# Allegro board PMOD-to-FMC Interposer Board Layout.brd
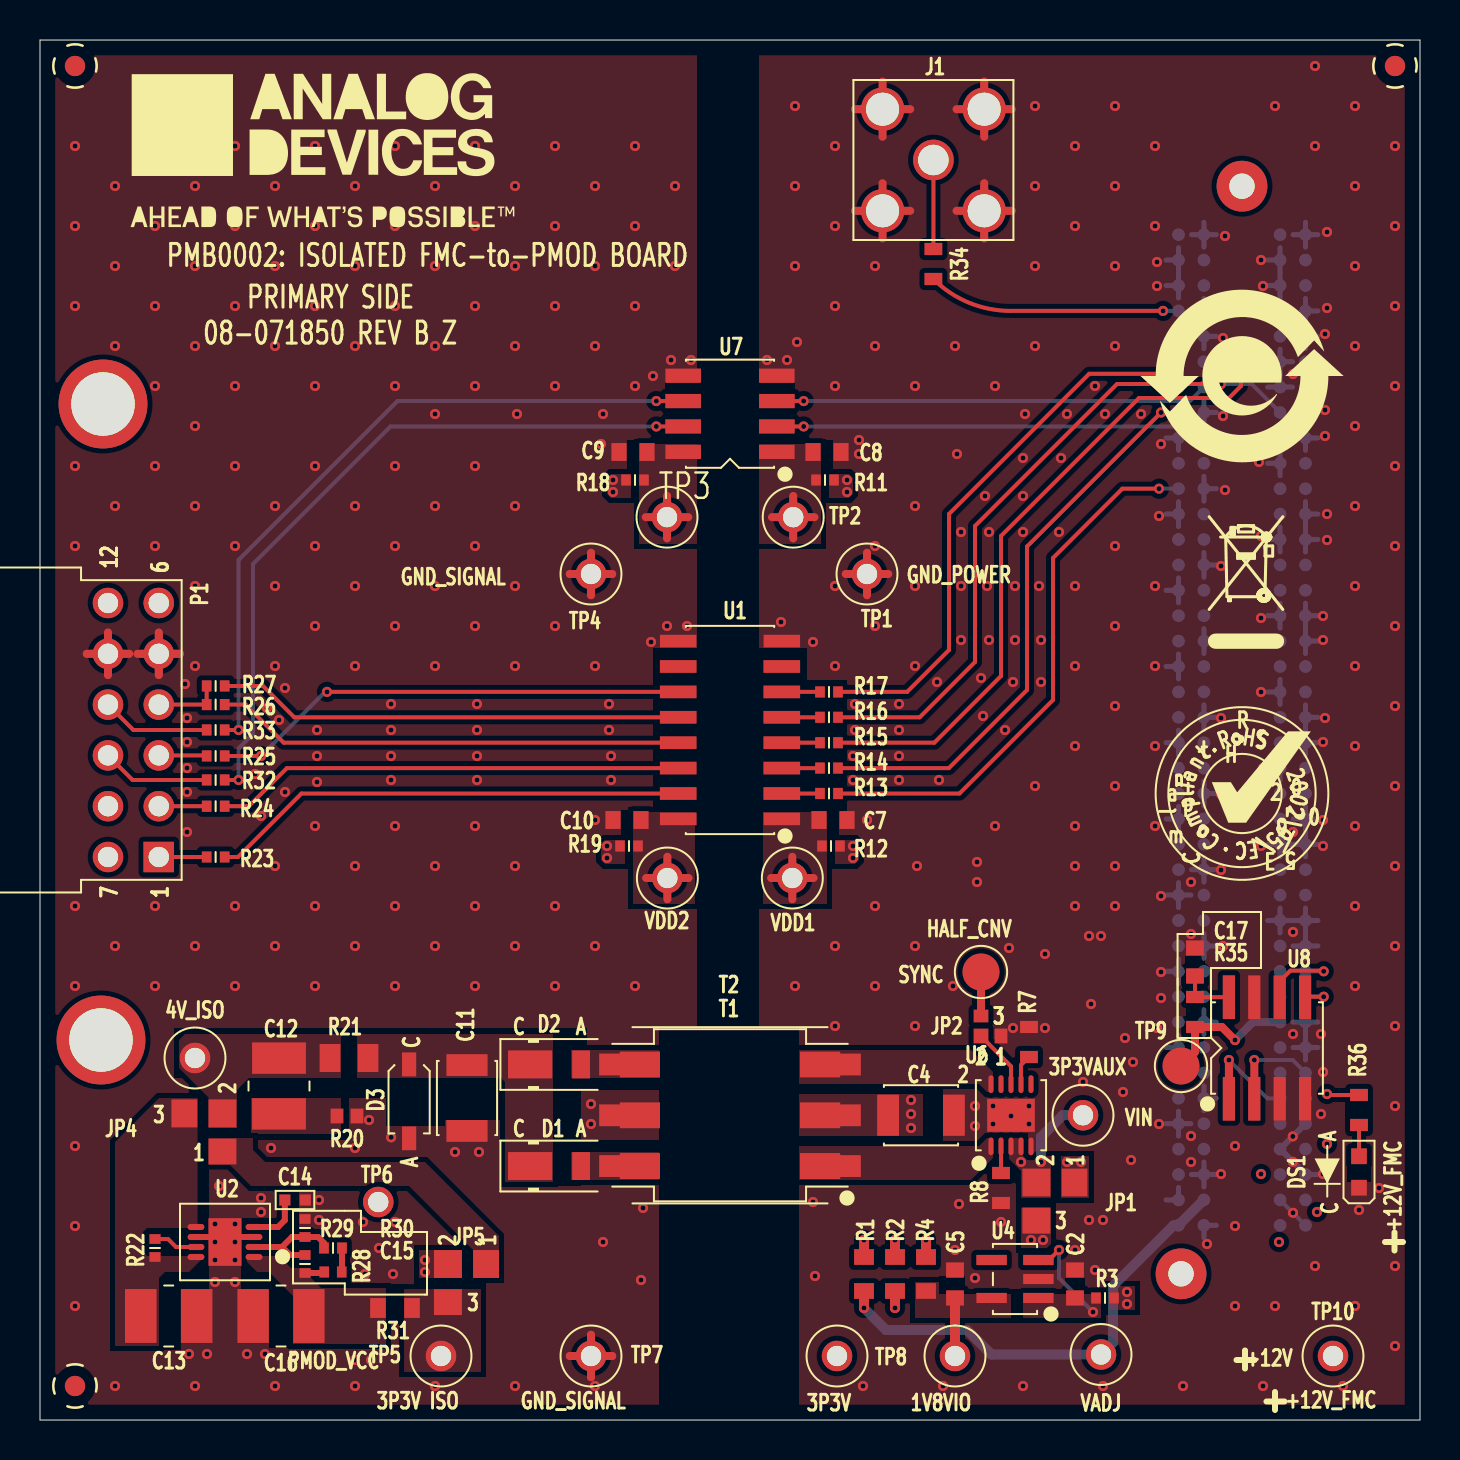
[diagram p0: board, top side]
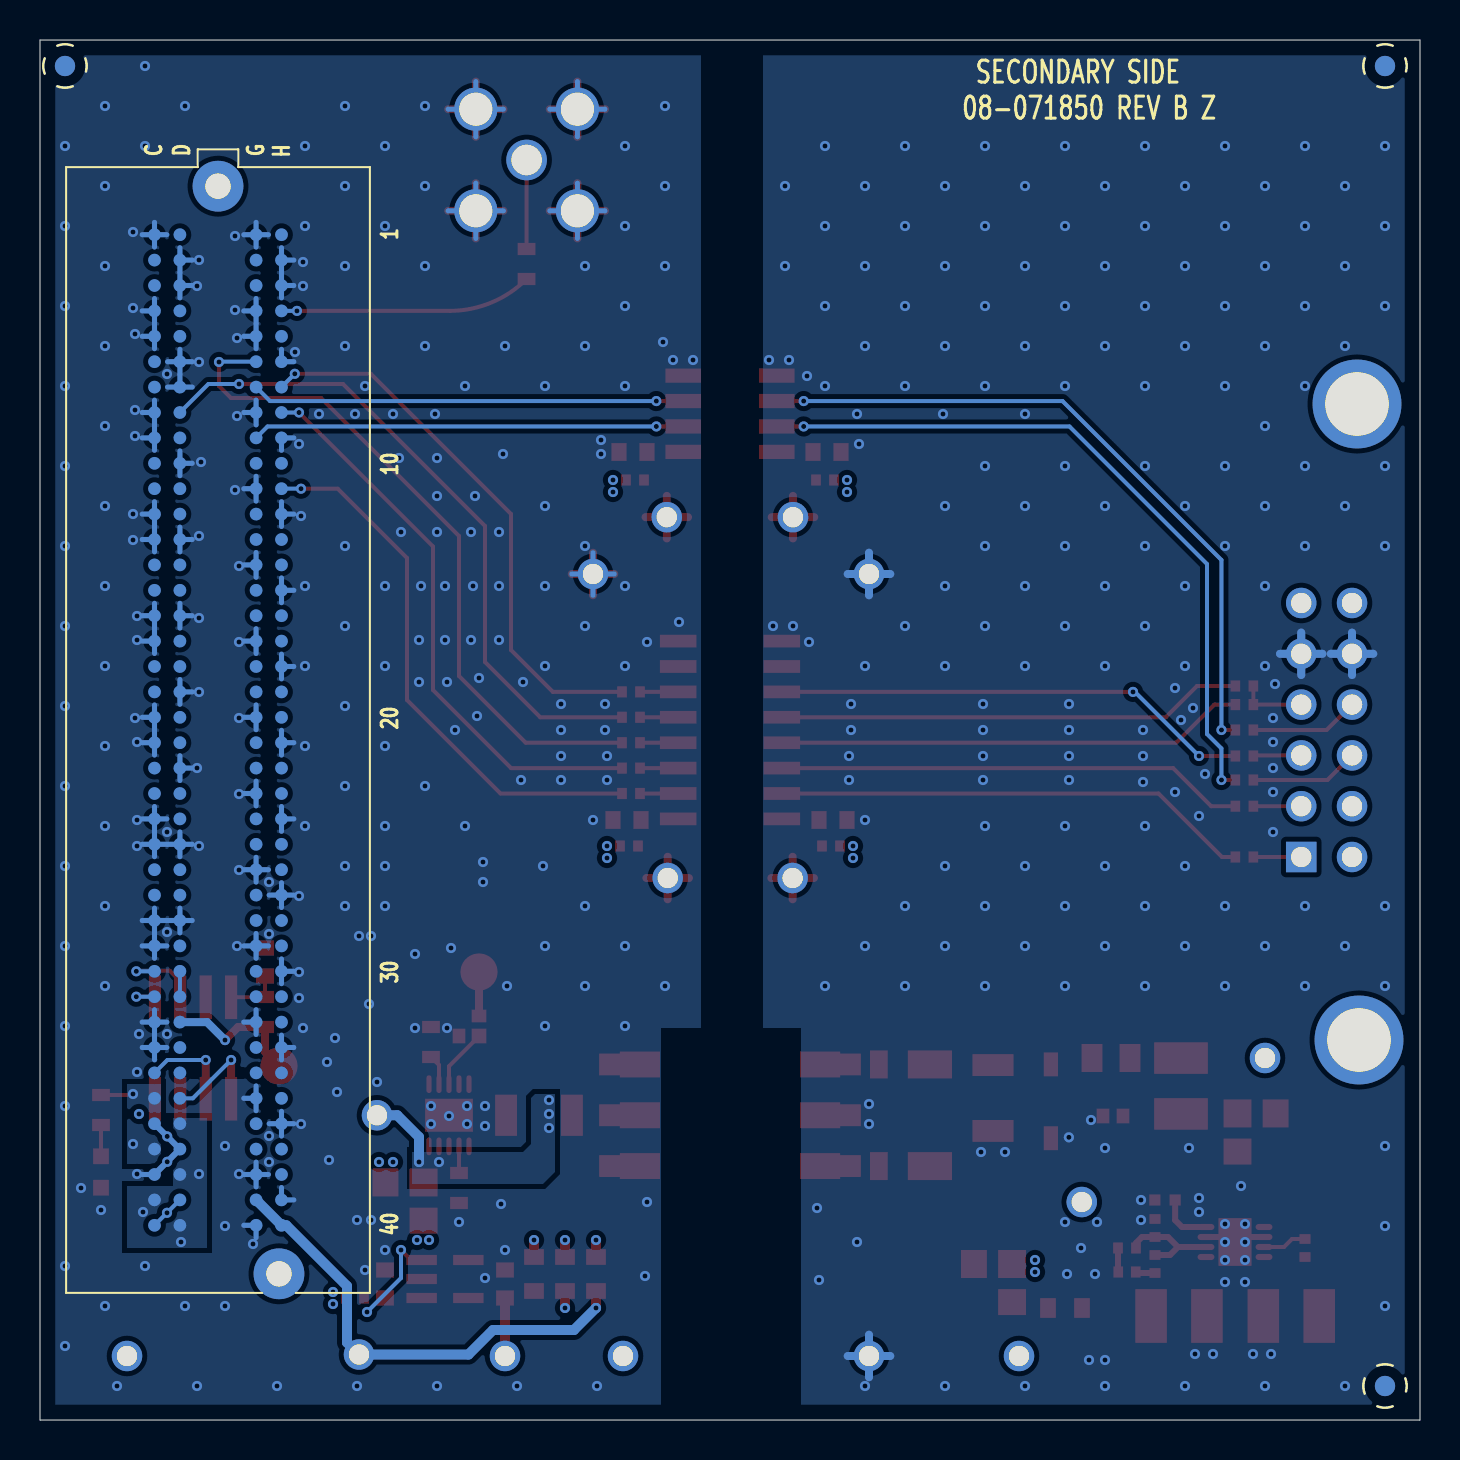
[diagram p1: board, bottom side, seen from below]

Outline 69 x 69 mm; copper layers: TOP, L2_GND, L3_PWR, BOTTOM. Coordinates in mm from the lower left corner of the outline.
Outline path: 0,69 69,69 69,0 0,0 0,69

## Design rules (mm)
constraint set DEFAULT: 

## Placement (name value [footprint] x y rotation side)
C2  1uF  [C0603]  51.75 6.8 90 top
C4  10uF  [C1210H106]  44.05 15.24 0 top
C5  1uF  [C0603]  45.75 6.8 90 top
C7  0.1uF  [C0603]  39.65 30 0 top
C8  0.1uF  [C0603]  39.35 48.4 0 top
C9  0.1uF  [C0603]  29.65 48.4 180 top
C10  0.1uF  [C0603]  29.35 30 180 top
C11  10uF  [C1210H106]  21.35 16.1 270 top
C12  4.7uF  [C1210-2]  11.95 16.7 270 top
C13  4.7uF  [C1210-2]  6.44 5.2 0 top
C14  1NF  [C0402]  12.75 11 0 top
C15  TBD0402  [C0402#2]  14.65 7.4 0 top
C16  4.7uF  [C1210-2]  12.05 5.2 180 top
C17  0.1uF  [C0603]  57.75 22.9 270 top
D1  DFLS240L-7  [POWERDI123]  25.45 12.7 0 top
D2  DFLS240L-7  [POWERDI123]  25.45 17.78 0 top
D3  CMHZ5236B  [SOD123-3]  18.46 15.93 270 top
DS1  SML-LX0603GW-TR  [LED0603-2]  65.95 12.4 90 top
J1  5-1814832-2  [CNTYCO1814832]  44.67 63 180 top
JP1  0  [3PINJUMPER_0603]  50.77 11.88 180 top
JP2  0  [3PINJUMPER_0402]  47.05 19.2 270 top
JP4  0  [3PINJUMPER_0603]  9.12 14.38 90 top
JP5  0  [3PINJUMPER_0603]  21.35 7.8 180 top
NOREF  -  []  0 69 270 top
NOREF#2  -  []  60.1 38.62 0 top
NOREF#3  -  []  90.1 114.4 0 top
NOREF#4  -  [unnamed#2]  1.75 67.7 0 top
NOREF#5  -  []  -62.9 -34.1 0 top
NOREF#6  -  []  156.1 301.8 0 top
NOREF#7  -  []  0.93 50.75 0 top
NOREF#8  -  []  56.4 143.2 0 top
NOREF#9  -  []  69 0 90 top
NOREF#10  -  []  0 69 0 top
NOREF#11  -  []  14.15 63.47 0 top
NOREF#12  -  []  0 69 0 top
NOREF#13  -  []  34.5 85.15 0 top
NOREF#14  -  [unnamed#2]  3.15 50.8 0 top
NOREF#15  -  [unnamed#2]  1.75 1.7 0 top
NOREF#16  -  []  69 69 180 top
NOREF#17  -  []  69 0 90 top
NOREF#18  -  []  69 0 0 top
NOREF#19  -  []  60.1 52.2 0 top
NOREF#20  -  []  0 0 0 top
NOREF#21  -  []  33.8 344.5 0 top
NOREF#22  -  []  0 0 0 top
NOREF#23  -  [unnamed#2]  67.75 67.7 0 top
NOREF#24  -  [unnamed#2]  3.05 19 0 top
NOREF#25  -  []  60.1 31.32 0 top
NOREF#26  -  []  0 0 0 top
NOREF#27  -  []  -112.8 -103 0 top
NOREF#28  -  [unnamed#2]  1.75 67.7 180 bottom
NOREF#29  -  [unnamed#2]  1.75 1.7 180 bottom
NOREF#30  -  [unnamed#2]  67.75 67.7 180 bottom
P1  PPPC062LJBN-RC  [CNHDRRA2X6H205]  5.94 28.15 90 top
P2  ASP-134604-01  [CNSAMTECASP-134604-01]  60.1 34.5 270 bottom
R1  0  [R0603]  41.2 7.3 90 top
R2  0  [R0603]  42.75 7.3 90 top
R3  0  [R0402]  53.25 6.1 180 top
R4  0  [R0603]  44.3 7.3 90 top
R7  36.5K  [R0603]  49.45 18.9 90 top
R8  49.9K  [R0603]  48.05 11.6 270 top
R11  0  [R0402]  39.25 47 180 top
R12  0  [R0402]  39.55 28.7 180 top
R13  0  [R0402]  39.45 31.32 180 top
R14  0  [R0402]  39.45 32.59 180 top
R15  0  [R0402]  39.45 33.87 180 top
R16  0  [R0402]  39.45 35.13 180 top
R17  0  [R0402]  39.45 36.41 180 top
R18  0  [R0402]  29.75 47 180 top
R19  0  [R0402]  29.45 28.7 180 top
R20  0  [R0402]  15.35 15.2 0 top
R21  0  [R0805]  15.45 18.1 180 top
R22  100K  [R0402]  5.75 8.6 90 top
R23  0  [R0402]  8.78 28.15 180 top
R24  0  [R0402]  8.78 30.69 180 top
R25  0  [R0402]  8.78 33.2 180 top
R26  0  [R0402]  8.78 35.77 180 top
R27  0  [R0402]  8.78 36.7 180 top
R28  0  [R0402]  13.25 7.8 90 top
R29  TBD0402  [R0402]  13.25 9.6 90 top
R30  TBD0402  [R0402]  14.65 8.6 0 top
R31  0  [R0603]  17.75 5.6 0 top
R32  0  [R0402]  8.78 32 0 top
R33  0  [R0402]  8.78 34.5 0 top
R34  TBD0603  [R0603]  44.67 57.8 270 top
R35  0  [R0603]  57.75 20.4 90 top
R36  2.4K  [R0603]  65.95 15.5 270 top
SYNC  4956-1-00-15-00-00-33-0  [CNMILLMAX4956]  47.05 22.4 0 top
T1  PH9085.083NLT  [TSML319W280H200]  34.5 15.24 90 top
T2  750315371  [TSML364W327H161]  34.5 15.24 180 top
TP1  BLK  [CNKEY5001TP]  41.35 42.3 90 top
TP2  RED  [CNKEY5001TP]  37.66 45.14 0 top
TP3  RED  [CNKEY5001TP]  31.35 45.14 0 top
TP4  BLK  [CNKEY5001TP]  27.55 42.3 0 top
TP5  RED  [CNKEY5001TP]  20.05 3.2 0 top
TP6  RED  [CNKEY5001TP]  16.91 10.9 0 top
TP7  BLK  [CNKEY5001TP]  27.55 3.2 0 top
TP8  RED  [CNKEY5001TP]  39.85 3.2 0 top
TP9  4956-1-00-15-00-00-33-0  [CNMILLMAX4956]  57.05 17.7 0 top
TP10  RED  [CNKEY5001TP]  64.65 3.2 0 top
U1  ADUM152N1BRZ  [SO16NB-2]  34.5 34.5 90 top
U2  ADP7105ACPZ-3.3  [DFN8_3X3_PAD2_38X1_64]  9.25 8.9 90 top
U4  ADP150AUJZ-1.8  [TSOT-5]  48.75 7.05 90 top
U6  LT3999EDD#PBF  [DFN10_3X3_PAD2_38X1_64]  48.55 15.24 0 top
U7  ADUM120N0BRZ  [SO8-2]  34.5 50.31 90 top
U8  M24C02-WMN6TP  [SO8]  61.35 18.6 0 top
UNK1V8VIO  RED  [CNKEY5001TP]  45.75 3.2 0 top
UNK4V_ISO  RED  [CNKEY5001TP]  7.75 18.1 0 top
VADJ  RED  [CNKEY5001TP]  53.05 3.27 180 top
VDD1  RED  [CNKEY5001TP]  37.62 27.1 0 top
VDD2  RED  [CNKEY5001TP]  31.37 27.1 0 top
VIN  RED  [CNKEY5001TP]  52.15 15.24 0 top

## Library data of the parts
C2 C5 = CAP: User Part Number: UPN; Tolerance: 10; alternate symbols: (C0603L); part number: CAP_SM-1UF,16V,10,E020111,C0603; tolerance: 10
C4 C11 = CAP: Tolerance: 10; User Part Number: UPN; alternate symbols: (); part number: CAP_SM-10UF,25V,10,E013830,C1210H106; tolerance: 10
C7-C10 = CAP: User Part Number: UPN; Tolerance: 10; alternate symbols: (C0603L); part number: CAP_SM-0.1UF,25V,10,E013746,C0603; tolerance: 10
C12 C13 C16 = CAP: Tolerance: 10; User Part Number: UPN; alternate symbols: (); part number: CAP_SM-4.7UF,50V,10,E030852,C1210-2; tolerance: 10
C14 = CAP: User Part Number: UPN; Tolerance: 10; alternate symbols: (C0402L); part number: CAP_SM-1NF,25V,10,E042764,C0402; tolerance: 10
C15 = CAP: User Part Number: UPN; alternate symbols: (C0402L_ALT,C0402L); part number: CAP_SM-TBD0402,TBD0402,TBD0402,E000381,C0402
C17 = CAP: User Part Number: UPN; Tolerance: 10; alternate symbols: (C0603L); part number: CAP_SM-0.1UF,50V,10,E011865,C0603; tolerance: 10
D1 D2 = DIOSCHOTTKY: User Part Number: UPN; Tolerance: N/A; alternate symbols: (); part number: DIOSCHOTTKY_SM-DFLS240L-7,40V,N/A,E022336,POWERDI123; tolerance: N/A
D3 = DIOZNR: Tolerance: 5; User Part Number: UPN; alternate symbols: (); part number: DIOZNR_SM-CMHZ5236B,7.5V,5,E033510,SOD123-3; tolerance: 5
DS1 = DIOLED: Tolerance: N/A; User Part Number: UPN; alternate symbols: (); part number: DIOLED_SM-SML-LX0603GW-TR,N/A,N/A,E018702,LED0603-2; tolerance: N/A
J1 = CNBNC5P: Tolerance: N/A; User Part Number: UPN; alternate symbols: (); part number: CNBNC5P_TH-5-1814832-2,E010606,CNTYCO1814832; tolerance: N/A
JP1 JP4 JP5 = RESJMPRSHRT_3P: Tolerance: JUMPER; User Part Number: UPN; alternate symbols: (); part number: RESJMPRSHRT_3P_SM-0,E004207,1/10W,JUMPER,3PINJUMPER_0603; tolerance: JUMPER
JP2 = RESJMPR_3P: User Part Number: UPN; Tolerance: JUMPER; alternate symbols: (3PINJUMPER_0402_AB, 3PINJUMPER_0402_BA); part number: RESJMPR_3P_SM-0,E003438,1/10W,JUMPER,3PINJUMPER_0402; tolerance: JUMPER
P1 = CN12P_V3: User Part Number: UPN; Tolerance: N/A; alternate symbols: (); part number: CN12P_V3_TH-PPPC062LJBN-RC,E022332,CNHDRRA2X6H205; tolerance: N/A
P2 = CN160P_CDGH_V2: User Part Number: UPN; Tolerance: N/A; alternate symbols: (CNSAMTECASP-134604-01_KITTRF,CNSAMTECASP-134604-01_EVKP); part number: CN160P_CDGH_V2_SM-ASP-134604-01,E011383,CNSAMTECASP-134604-01; tolerance: N/A
R1 R2 R4 R31 = RES: User Part Number: UPN; Tolerance: JUMPER; alternate symbols: (R0603L); part number: RES_SM-0,E006826,1/10W,JUMPER,R0603; tolerance: JUMPER
R3 R11-R20 R23-R28 R32 R33 = RES: User Part Number: UPN; Tolerance: JUMPER; alternate symbols: (R0402L,R0402L_ALT); part number: RES_SM-0,E003438,1/10W,JUMPER,R0402; tolerance: JUMPER
R7 = RES: User Part Number: UPN; Tolerance: 1; alternate symbols: (R0603L); part number: RES_SM-36.5K,E011130,1/10W,1,R0603; tolerance: 1
R8 = RES: User Part Number: UPN; Tolerance: 1; alternate symbols: (R0603L); part number: RES_SM-49.9K,E022444,1/4W,1,R0603; tolerance: 1
R21 = RES: User Part Number: UPN; Tolerance: JUMPER; alternate symbols: (R0805L); part number: RES_SM-0,E030875,1/8W,JUMPER,R0805; tolerance: JUMPER
R22 = RES: User Part Number: UPN; Tolerance: 1; alternate symbols: (R0402L,R0402L_ALT); part number: RES_SM-100K,E003796,1/10W,1,R0402; tolerance: 1
R29 R30 = RES: User Part Number: UPN; alternate symbols: (R0402L,R0402L_ALT); part number: RES_SM-TBD0402,E004049,TBD0402,TBD0402,R0402
R34 = RES: User Part Number: UPN; alternate symbols: (R0603L); part number: RES_SM-TBD0603,E004050,TBD0603,TBD0603,R0603
R35 = RES: User Part Number: UPN; Tolerance: JUMPER; alternate symbols: (R0603L); part number: RES_SM-0,E034483,1/10W,JUMPER,R0603; tolerance: JUMPER
R36 = RES: User Part Number: UPN; Tolerance: 1; alternate symbols: (R0603L); part number: RES_SM-2.4K,E010182,1/10W,1,R0603; tolerance: 1
SYNC TP9 = CNTP1P: Tolerance: N/A; User Part Number: UPN; alternate symbols: (); part number: CNTP1P_SM-4956-1-00-15-00-00-33-0,E043669,CNMILLMAX4956; tolerance: N/A
T1 = XFMR6P_V16: User Part Number: UPN; Tolerance: N/A; alternate symbols: (); part number: XFMR6P_V16_SM-PH9085.083NLT,E059271,TSML319W280H200; tolerance: N/A
T2 = XFMR6P_V16: User Part Number: UPN; Tolerance: N/A; alternate symbols: (); part number: XFMR6P_V16_SM-750315371,E059270,TSML364W327H161; tolerance: N/A
TP1 TP4 TP7 = CNTP1P: Tolerance: N/A; User Part Number: UPN; alternate symbols: (); part number: CNTP1P_TH-BLK,E022951,CNKEY5001TP; tolerance: N/A
TP2 TP3 TP5 TP6 TP8 TP10 UNK1V8VIO UNK4V_ISO VADJ VDD1 VDD2 VIN = CNTP1P: Tolerance: N/A; User Part Number: UPN; alternate symbols: (); part number: CNTP1P_TH-RED,E016323,CNKEY5001TP; tolerance: N/A
U1 = ADUM152N: Tolerance: N/A; User Part Number: UPN; alternate symbols: (); part number: ADUM152N_SM-ADUM152N1BRZ,E057835,SO16NB-2; tolerance: N/A
U2 = ADP7105: Tolerance: N/A; User Part Number: UPN; alternate symbols: (); part number: ADP7105_SM-ADP7105ACPZ-3.3,E019351,DFN8_3X3_PAD2_38X1_64; tolerance: N/A
U4 = ADP150: User Part Number: UPN; Tolerance: N/A; alternate symbols: (); part number: ADP150_SM-ADP150AUJZ-1.8,E030683,TSOT-5; tolerance: N/A
U6 = ADLT3999: Tolerance: N/A; User Part Number: UPN; alternate symbols: (); part number: ADLT3999_SM-LT3999EDD#PBF,E039116,DFN10_3X3_PAD2_38X1_64; tolerance: N/A
U7 = ADUM120N: Tolerance: N/A; User Part Number: UPN; alternate symbols: (); part number: ADUM120N_SM-ADUM120N0BRZ,E033382,SO8-2; tolerance: N/A
U8 = ICM24CXX: User Part Number: UPN; Tolerance: N/A; alternate symbols: (); part number: ICM24CXX_SM-M24C02-WMN6TP,E017528,SO8; tolerance: N/A

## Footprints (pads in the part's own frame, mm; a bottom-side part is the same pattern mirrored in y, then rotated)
3PINJUMPER_0402
  rect 0.737x0.635 smd: 1(0,1.001)
  rect 0.737x0.737 smd: 2(0,0)
  rect 0.635x0.737 smd: 3(-1.001,0)
3PINJUMPER_0603
  rect 1.295x1.397 smd: 1(-0.953,0)
  rect 1.397x1.397 smd: 2(0.953,0)
  rect 1.397x1.295 smd: 3(0.953,1.905)
C0402
  rect 0.559x0.559 smd: 1(-0.508,0) 2(0.508,0)
C0402#2
  rect 0.483x0.559 smd: 1(-0.438,0) 2(0.438,0)
C0603
  rect 0.762x0.889 smd: 1(-0.7,0) 2(0.7,0)
C1210-2
  rect 1.575x2.692 smd: 1(-1.397,0) 2(1.397,0)
C1210H106
  rect 1.092x2.057 smd: 1(-1.646,0) 2(1.646,0)
CNHDRRA2X6H205
  rect 1.524x1.524 hole 1.016: 1(0,0)
  round 1.524 hole 1.016: 2(2.54,0) 3(5.08,0) 4(7.62,0) 5(10.16,0) 6(12.7,0) 7(0,2.54) 8(2.54,2.54) 9(5.08,2.54) 10(7.62,2.54) 11(10.16,2.54) 12(12.7,2.54)
CNKEY5001TP
  round 1.524 hole 1.016: 1(0,0)
CNMILLMAX4956
  round 1.854 smd: 1(0,0)
CNSAMTECASP-134604-01
  round 2.54 hole 1.27 unplated: (-27.191,0) (27.191,3.048)
  round 0.635 smd: C1(-24.765,-3.175) C2(-23.495,-3.175) C3(-22.225,-3.175) C4(-20.955,-3.175) C5(-19.685,-3.175) C6(-18.415,-3.175) C7(-17.145,-3.175) C8(-15.875,-3.175) C9(-14.605,-3.175) C10(-13.335,-3.175) C11(-12.065,-3.175) C12(-10.795,-3.175) C13(-9.525,-3.175) C14(-8.255,-3.175) C15(-6.985,-3.175) C16(-5.715,-3.175) C17(-4.445,-3.175) C18(-3.175,-3.175) C19(-1.905,-3.175) C20(-0.635,-3.175) C21(0.635,-3.175) C22(1.905,-3.175) C23(3.175,-3.175) C24(4.445,-3.175) C25(5.715,-3.175) C26(6.985,-3.175) C27(8.255,-3.175) C28(9.525,-3.175) C29(10.795,-3.175) C30(12.065,-3.175) C31(13.335,-3.175) C32(14.605,-3.175) C33(15.875,-3.175) C34(17.145,-3.175) C35(18.415,-3.175) C36(19.685,-3.175) C37(20.955,-3.175) C38(22.225,-3.175) C39(23.495,-3.175) C40(24.765,-3.175) D1(-24.765,-1.905) D2(-23.495,-1.905) D3(-22.225,-1.905) D4(-20.955,-1.905) D5(-19.685,-1.905) D6(-18.415,-1.905) D7(-17.145,-1.905) D8(-15.875,-1.905) D9(-14.605,-1.905) D10(-13.335,-1.905) D11(-12.065,-1.905) D12(-10.795,-1.905) D13(-9.525,-1.905) D14(-8.255,-1.905) D15(-6.985,-1.905) D16(-5.715,-1.905) D17(-4.445,-1.905) D18(-3.175,-1.905) D19(-1.905,-1.905) D20(-0.635,-1.905) D21(0.635,-1.905) D22(1.905,-1.905) D23(3.175,-1.905) D24(4.445,-1.905) D25(5.715,-1.905) D26(6.985,-1.905) D27(8.255,-1.905) D28(9.525,-1.905) D29(10.795,-1.905) D30(12.065,-1.905) D31(13.335,-1.905) D32(14.605,-1.905) D33(15.875,-1.905) D34(17.145,-1.905) D35(18.415,-1.905) D36(19.685,-1.905) D37(20.955,-1.905) D38(22.225,-1.905) D39(23.495,-1.905) D40(24.765,-1.905) G1(-24.765,1.905) G2(-23.495,1.905) G3(-22.225,1.905) G4(-20.955,1.905) G5(-19.685,1.905) G6(-18.415,1.905) G7(-17.145,1.905) G8(-15.875,1.905) G9(-14.605,1.905) G10(-13.335,1.905) G11(-12.065,1.905) G12(-10.795,1.905) G13(-9.525,1.905) G14(-8.255,1.905) G15(-6.985,1.905) G16(-5.715,1.905) G17(-4.445,1.905) G18(-3.175,1.905) G19(-1.905,1.905) G20(-0.635,1.905) G21(0.635,1.905) G22(1.905,1.905) G23(3.175,1.905) G24(4.445,1.905) G25(5.715,1.905) G26(6.985,1.905) G27(8.255,1.905) G28(9.525,1.905) G29(10.795,1.905) G30(12.065,1.905) G31(13.335,1.905) G32(14.605,1.905) G33(15.875,1.905) G34(17.145,1.905) G35(18.415,1.905) G36(19.685,1.905) G37(20.955,1.905) G38(22.225,1.905) G39(23.495,1.905) G40(24.765,1.905) H1(-24.765,3.175) H2(-23.495,3.175) H3(-22.225,3.175) H4(-20.955,3.175) H5(-19.685,3.175) H6(-18.415,3.175) H7(-17.145,3.175) H8(-15.875,3.175) H9(-14.605,3.175) H10(-13.335,3.175) H11(-12.065,3.175) H12(-10.795,3.175) H13(-9.525,3.175) H14(-8.255,3.175) H15(-6.985,3.175) H16(-5.715,3.175) H17(-4.445,3.175) H18(-3.175,3.175) H19(-1.905,3.175) H20(-0.635,3.175) H21(0.635,3.175) H22(1.905,3.175) H23(3.175,3.175) H24(4.445,3.175) H25(5.715,3.175) H26(6.985,3.175) H27(8.255,3.175) H28(9.525,3.175) H29(10.795,3.175) H30(12.065,3.175) H31(13.335,3.175) H32(14.605,3.175) H33(15.875,3.175) H34(17.145,3.175) H35(18.415,3.175) H36(19.685,3.175) H37(20.955,3.175) H38(22.225,3.175) H39(23.495,3.175) H40(24.765,3.175)
CNTYCO1814832
  round 2.032 hole 1.524: 1(0,0)
  round 2.159 hole 1.651: 2(-2.54,2.54) 3(2.54,2.54) 4(2.54,-2.54) 5(-2.54,-2.54)
DFN8_3X3_PAD2_38X1_64
  oval 0.305x0.838 smd: 1(-0.75,-1.45) 2(-0.25,-1.45) 3(0.25,-1.45) 4(0.75,-1.45) 5(0.75,1.45) 6(0.25,1.45) 7(-0.25,1.45) 8(-0.75,1.45)
  rect 2.388x1.651 smd: PAD(0,0)
DFN10_3X3_PAD2_38X1_64
  oval 0.254x0.889 smd: 1(-1,-1.556) 2(-0.5,-1.556) 3(0,-1.556) 4(0.5,-1.556) 5(1,-1.556) 6(1,1.556) 7(0.5,1.556) 8(0,1.556) 9(-0.5,1.556) 10(-1,1.556)
  rect 2.388x1.651 smd: PAD(0,0)
LED0603-2
  rect 0.787x0.787 smd: A(0.787,0) C(-0.787,0)
POWERDI123
  rect 0.889x1.397 smd: A(1.605,0)
  rect 2.21x1.397 smd: C(-0.945,0)
R0402
  rect 0.483x0.559 smd: 1(-0.45,0) 2(0.45,0)
R0603
  rect 0.787x0.991 smd: 1(-0.85,0) 2(0.85,0)
R0805
  rect 1.041x1.397 smd: 1(-0.95,0) 2(0.95,0)
SO8
  rect 0.61x2.184 smd: 1(-1.905,-2.54) 2(-0.635,-2.54) 3(0.635,-2.54) 4(1.905,-2.54) 5(1.905,2.54) 6(0.635,2.54) 7(-0.635,2.54) 8(-1.905,2.54)
SO8-2
  rect 0.711x1.778 smd: 1(-1.905,-2.341) 2(-0.635,-2.341) 3(0.635,-2.341) 4(1.905,-2.341) 5(1.905,2.341) 6(0.635,2.341) 7(-0.635,2.341) 8(-1.905,2.341)
SO16NB-2
  rect 0.635x1.829 smd: 1(-4.445,-2.591) 2(-3.175,-2.591) 3(-1.905,-2.591) 4(-0.635,-2.591) 5(0.635,-2.591) 6(1.905,-2.591) 7(3.175,-2.591) 8(4.445,-2.591) 9(4.445,2.591) 10(3.175,2.591) 11(1.905,2.591) 12(0.635,2.591) 13(-0.635,2.591) 14(-1.905,2.591) 15(-3.175,2.591) 16(-4.445,2.591)
SOD123-3
  rect 1.194x0.711 smd: A(1.847,0) C(-1.847,0)
TSML319W280H200
  rect 1.295x2.007 smd: 1(-2.54,-4.503) 2(0,-4.503) 3(2.54,-4.503) 4(2.54,4.503) 5(0,4.503) 6(-2.54,4.503)
TSML364W327H161
  rect 1.829x1.092 smd: 1(-5.626,2.54) 2(-5.626,0) 3(-5.626,-2.54) 4(5.626,-2.54) 5(5.626,0) 6(5.626,2.54)
TSOT-5
  rect 0.508x1.524 smd: 1(-0.95,-1.17) 2(0,-1.17) 3(0.95,-1.17) 4(0.95,1.17) 5(-0.95,1.17)
unnamed#2
  round 1.016 smd: (0,0)

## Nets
1V8VIO_FMC: C5.1 R4.1 U4.5(VOUT) UNK1V8VIO.1
4V_ISO: C12.1 JP4.2(COM) R21.2(N2) UNK4V_ISO.1
+12V_FMC: JP1.1 P2.C35 P2.C37 R36.1 TP10.1(N1)
GND_POWER: C2.2(N2) C4.2(N2) C5.2(N2) C7.2(N2) C8.2(N2) C17.1 DS1.C J1.2 J1.3 J1.4 J1.5(SH4) JP2.1 P2.C1 P2.C4 P2.C5 P2.C8 P2.C9 P2.C12 P2.C13 P2.C16 P2.C17 P2.C20 P2.C21 P2.C24 P2.C25 P2.C28 P2.C29 P2.C32 P2.C33 P2.C36 P2.C38 P2.C40 P2.D2 P2.D3 P2.D6 P2.D7 P2.D10 P2.D13 P2.D16 P2.D19 P2.D22 P2.D25 P2.D28 P2.D37 P2.D39 P2.G1 P2.G4 P2.G5 P2.G8 P2.G11 P2.G14 P2.G17 P2.G20 P2.G23 P2.G26 P2.G29 P2.G32 P2.G35 P2.G38 P2.G40 P2.H2 P2.H3 P2.H6 P2.H9 P2.H12 P2.H15 P2.H18 P2.H21 P2.H24 P2.H27 P2.H30 P2.H33 P2.H36 P2.H39 R7.2(N2) R8.2(N2) TP1.1(N1) U1.8 U4.2 U6.5 U6.PAD U7.4 U8.3 U8.4 U8.7(WC_N)
GND_SIGNAL: C9.2(N2) C10.2(N2) C11.2(N2) C13.2(N2) C14.2(N2) C16.2(N2) D3.A(P) P1.5 P1.11 R20.2(N2) R29.2(N2) T1.5(SEC_CT) T2.5(SEC_CT) TP4.1(N1) TP7.1(N1) U1.9 U2.3 U2.6 U2.PAD U7.5
3P3V_FMC: JP1.3 P2.C39 P2.D36 P2.D38 P2.D40 R2.1 R3.1 TP8.1(N1)
3P3V_ISO: C15.1 C16.1 R28.1 R31.1 U2.1(VOUT)
3P3VAUX: P2.D32 R35.1 TP9.1(N1)
CLK0_M2C_P: P2.H4 R34.2(N2)
CNV: P1.1 R23.2(N2)
CNV_FMC: P2.H11 R13.1
CNV_ISO: R23.1 U1.15
FMC_VIO: R1.2(N2) R2.2(N2) R4.2(N2) R11.1 R12.1
GA0: P2.C34 U8.2
GA1: P2.D35 U8.1
LT3999_SYNC: JP2.2(COM) U6.8
MUX_A0: P1.9 R32.1
MUX_A0_FMC: P2.G9 U7.2
MUX_A0_ISO: R32.2(N2) U7.7
MUX_A1: P1.10 R33.1
MUX_A1_FMC: P2.G7 U7.3
MUX_A1_ISO: R33.2(N2) U7.6(VOB)
PMOD_VCC: JP5.2(COM) P1.6 P1.12(VCC2) R18.2(N2) R19.2(N2) TP6.1(N1)
SCLK: P1.4 R26.2(N2) R27.2(N2)
SCLK_FMC: P2.G6 R15.1
SCLK_ISO: R26.1 U1.13
SCLK_RET_FMC: P2.D8 R16.1
SCLK_RETURN: R27.1 U1.12
SDI: P1.2 R24.2(N2)
SDI_FMC: P2.H8 R14.1
SDI_ISO: R24.1 U1.14
SDO: P1.3 R25.2(N2)
SDO_FMC: P2.H7 R17.1
SDO_ISO: R25.1 U1.11
UNNAMED_7_ADLT3999_I29_RBIAS: R8.1 U6.2
UNNAMED_7_ADLT3999_I29_RT: R7.1 U6.7
UNNAMED_7_ADP7105_I140_PG: R22.2(N2) U2.7
UNNAMED_7_ADP7105_I140_SENSE: R28.2(N2) R29.1 R30.1 U2.2
UNNAMED_7_ADP7105_I140_SS: C14.1 U2.4
UNNAMED_7_ADP7105_I140_VIN: C13.1 JP4.3 R22.1 U2.5 U2.8
UNNAMED_7_ADUM120N_I19_VDD1: C8.1 R11.2(N2) TP2.1(N1) U7.1
UNNAMED_7_ADUM120N_I19_VDD2: C9.1 R18.1 TP3.1(N1) U7.8
UNNAMED_7_ADUM152N_I128_VIA: R13.2(N2) U1.2
UNNAMED_7_ADUM152N_I128_VIB: R14.2(N2) U1.3
UNNAMED_7_ADUM152N_I128_VIC: R15.2(N2) U1.4
UNNAMED_7_ADUM152N_I128_VOD: R16.2(N2) U1.5
UNNAMED_7_ADUM152N_I128_VOE: R17.2(N2) U1.6(VOE)
UNNAMED_7_CAP_I3_N1: C2.1 R3.2(N2) U4.1 U4.3
UNNAMED_7_CAP_I38_N1: C11.1 D1.C D2.C D3.C R21.1
UNNAMED_7_CAP_I51_N1: C10.1 R19.1 U1.16 VDD2.1(N1)
UNNAMED_7_CAP_I54_N1: C7.1 R12.2(N2) U1.1 VDD1.1(N1)
UNNAMED_7_CAP_I136_N2: C12.2(N2) R20.1
UNNAMED_7_CAP_I146_N2: C15.2(N2) R30.2(N2)
UNNAMED_7_CNTP1P_I189_N1: JP2.3 SYNC.1(N1)
UNNAMED_7_CNTP1P_I212_N1: JP5.3 R31.2(N2) TP5.1(N1)
UNNAMED_7_RESJMPRSHRT3P_I198_A: JP4.1 JP5.1
UNNAMED_8_CAP_I16_N2: C17.2(N2) R35.2(N2) U8.8
UNNAMED_8_CN160PCDGHV2_I11_TDI: P2.D30 P2.D31
UNNAMED_8_CN160PCDGHV2_I22_SCL: P2.C30 U8.6
UNNAMED_8_CN160PCDGHV2_I22_SDA: P2.C31 U8.5
UNNAMED_8_CNBNC5P_I2_CNTR: J1.1 R34.1
UNNAMED_8_DIOLED_I20_P: DS1.A(P) R36.2(N2)
VAJD_FMC: P2.G39 P2.H40 R1.1 VADJ.1(N1)
XP1: T1.1 T2.1 U6.1
XP2: C4.1 JP1.2(COM) T1.2 T2.2 U6.3(VIN) U6.4 VIN.1(N1)
XP3: T1.3 T2.3 U6.10
XP4: D2.A(P) T1.4 T2.4
XP6: D1.A(P) T1.6 T2.6

Pads without a net: P1 7 8; P2 C2 C3 C6 C7 C10 C11 C14 C15 C18 C19 C22 C23 C26 C27 D1 D4 D5 D9 D11 D12 D14 D15 D17 D18 D20 D21 D23 D24 D26 D27 D29 D33 D34 G2 G3 G10 G12 G13 G15 G16 G18 G19 G21 G22 G24 G25 G27 G28 G30 G31 G33 G34 G36 G37 H1 H5 H10 H13 H14 H16 H17 H19 H20 H22 H23 H25 H26 H28 H29 H31 H32 H34 H35 H37 H38; U1 7 10; U4 4; U6 6 9

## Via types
v1: diameter 0.508, hole 0.254, TOP to BOTTOM, 491 vias

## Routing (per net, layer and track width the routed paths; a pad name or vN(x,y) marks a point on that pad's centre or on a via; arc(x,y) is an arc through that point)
1V8VIO_FMC: length 2.9
  TOP w0.5: UNK1V8VIO.1 C5.1
+12V_FMC: length 5.9
  TOP w0.2: R36.1 64.4,16.25 v1(64.35,16.3)
  L3_PWR w0.4: TP10.1 65.71,3.2 ; TP10.1 64.65,2.14 ; TP10.1 63.59,3.2 ; TP10.1 64.65,4.26
  vias: v1(51.35,12.9) v1(52.05,12.9) v1(64.35,13.8)
GND_POWER: length 220.1
  TOP w0.4: 47.21,59.08 J1.2 ; J1.2 45.83,60.46 ; J1.2 47.21,61.84 ; J1.2 48.59,60.46 ; 47.21,64.16 J1.5 ; J1.5 47.21,66.92 ; J1.5 45.83,65.54 ; J1.5 48.59,65.54 ; 40.75,60.46 J1.3 ; J1.3 42.13,59.08 ; J1.3 43.51,60.46 ; J1.3 42.13,61.84 ; TP1.1 41.35,43.36 ; TP1.1 42.41,42.3 ; TP1.1 40.29,42.3 ; TP1.1 41.35,41.24 ; J1.4 42.13,66.92 ; J1.4 40.75,65.54 ; J1.4 42.13,64.16 ; J1.4 43.51,65.54
  L2_GND w0.4: TP1.1 41.35,43.36 ; TP1.1 40.29,42.3 ; TP1.1 42.41,42.3 ; TP1.1 41.35,41.24 ; 45.83,60.46 J1.2 ; J1.2 47.21,61.84 ; J1.2 47.21,59.08 ; J1.2 48.59,60.46 ; 40.75,65.54 J1.4 ; J1.4 43.51,65.54 ; J1.4 42.13,64.16 ; J1.4 42.13,66.92 ; J1.5 48.59,65.54 ; J1.5 47.21,66.92 ; J1.5 47.21,64.16 ; J1.5 45.83,65.54 ; 42.13,59.08 J1.3 ; J1.3 42.13,61.84 ; J1.3 43.51,60.46 ; J1.3 40.75,60.46
  L3_PWR w0.4: J1.3 43.51,60.46 ; J1.3 42.13,61.84 ; J1.3 42.13,59.08 ; J1.3 40.75,60.46 ; J1.5 47.21,66.92 ; J1.5 48.59,65.54 ; J1.5 47.21,64.16 ; J1.5 45.83,65.54 ; 42.13,64.16 J1.4 ; J1.4 40.75,65.54 ; J1.4 42.13,66.92 ; J1.4 43.51,65.54 ; 45.83,60.46 J1.2 ; J1.2 47.21,61.84 ; J1.2 47.21,59.08 ; J1.2 48.59,60.46
  BOTTOM w0.2: P2.C40 v1(62.65,10.36) P2.D39
  BOTTOM w0.254: P2.C8 63.89,50.38 ; P2.C8 63.27,49.76 ; P2.C8 63.27,50.99 ; 62.01,52.3 P2.D6 ; P2.D6 61.39,52.91 ; P2.D6 62.01,53.53 ; P2.D6 62.62,52.91 ; P2.C5 63.27,54.8 ; P2.C5 63.27,53.57 ; P2.C5 63.89,54.19 ; 57.58,27.52 P2.G26 ; P2.G26 58.2,28.13 ; P2.G26 58.2,26.9 ; P2.G26 58.81,27.52 ; P2.D28 62.01,25.59 ; P2.D28 62.62,24.98 ; P2.D28 62.01,24.36 ; P2.D28 61.39,24.98 ; P2.C21 63.89,33.87 ; P2.C21 63.27,33.25 ; P2.C21 63.27,34.48 ; 61.39,57.99 P2.D2 ; P2.D2 62.01,58.61 ; P2.D2 62.01,57.38 ; 58.2,23.09 P2.G29 ; P2.G29 58.2,24.32 ; P2.G29 57.58,23.7 ; P2.G29 58.81,23.7 ; P2.G11 58.81,46.56 ; P2.G11 58.2,47.18 ; P2.G11 58.2,45.95 ; 56.31,18.62 56.92,18.62 ; 56.92,18.62 56.92,18.01 ; 56.92,18.62 56.92,19.24 ; 42.13,59.08 J1.3 ; J1.3 40.75,60.46 ; J1.3 42.13,61.84 ; J1.3 43.51,60.46 ; 41.35,41.24 TP1.1 ; TP1.1 40.29,42.3 ; TP1.1 41.35,43.36 ; TP1.1 42.41,42.3 ; 56.92,26.25 56.92,26.86 ; 56.92,26.25 57.54,26.25 ; 56.92,26.25 56.31,26.25 ; 56.92,26.25 56.92,25.63 ; P2.G23 58.2,31.94 ; P2.G23 58.81,31.32 ; P2.G23 58.2,30.71 ; 58.2,9.12 P2.G40 58.81,9.73 ; 62.66,18.62 P2.C33 ; P2.C33 63.89,18.62 ; P2.C33 63.27,19.24 ; P2.C33 63.27,18.01 ; 57.58,12.28 58.2,12.28 ; 58.2,12.28 58.2,12.89 ; 58.2,12.28 58.81,12.28 ; 58.2,12.28 58.2,11.66 ; P2.C12 63.89,45.3 ; P2.C12 63.27,45.91 ; P2.C12 63.27,44.68 ; 56.92,11.62 56.92,11.01 56.31,11.01 ; 62.66,23.7 P2.C29 ; P2.C29 63.27,24.32 ; P2.C29 63.27,23.09 ; P2.C29 63.89,23.7 ; P2.G35 58.2,16.7 ; P2.G35 58.81,16.09 ; P2.G35 58.2,15.47 ; P2.D10 62.01,48.45 ; P2.D10 62.01,47.22 ; P2.D10 61.39,47.84 ; P2.C28 63.27,25.59 ; P2.C28 63.27,24.36 ; P2.C28 62.66,24.98 ; P2.C28 63.89,24.98 ; J1.5 48.59,65.54 ; J1.5 47.21,66.92 ; J1.5 47.21,64.16 ; J1.5 45.83,65.54 ; 63.27,38.33 P2.C17 ; P2.C17 63.89,38.95 ; P2.C17 63.27,39.56 ; 56.92,40.87 56.92,41.48 ; 56.92,41.48 56.31,41.48 ; 56.92,41.48 56.92,42.1 ; 56.92,57.38 56.92,57.99 ; 56.92,57.99 56.92,58.61 ; 56.92,57.99 56.31,57.99 ; P2.G8 58.81,50.38 ; P2.G8 58.2,49.76 ; P2.G8 58.2,50.99 ; 56.31,30.05 56.92,30.05 ; 56.92,30.05 56.92,29.44 ; 56.92,30.05 56.92,30.67 ; J1.4 42.13,66.92 ; J1.4 40.75,65.54 ; J1.4 42.13,64.16 ; J1.4 43.51,65.54 ; J1.2 48.59,60.46 ; J1.2 47.21,61.84 ; J1.2 47.21,59.08 ; J1.2 45.83,60.46 ; 62.01,39.6 P2.D16 ; P2.D16 61.39,40.22 ; P2.D16 62.01,40.83 ; 62.01,35.79 P2.D19 ; P2.D19 62.01,37.02 ; P2.D19 61.39,36.41 ; 61.39,51.65 P2.D7 ; P2.D7 62.62,51.65 ; P2.D7 62.01,52.26 ; 56.92,14.81 57.54,14.81 ; 56.92,14.81 56.92,15.43 ; 56.92,14.81 56.31,14.81 ; 56.92,14.81 56.92,14.2 ; 63.27,29.44 P2.C24 ; P2.C24 63.89,30.05 ; P2.C24 63.27,30.67 ; P2.C24 62.66,30.05 ; 58.2,58.65 P2.G1 ; P2.G1 57.58,59.27 ; P2.G1 58.2,59.88 ; P2.G1 58.81,59.27 ; 56.92,48.49 56.92,49.1 56.31,49.1 ; 56.31,52.91 56.92,52.91 56.92,53.53 ; 62.01,43.41 P2.D13 ; P2.D13 62.01,44.64 ; P2.D13 61.39,44.02 ; P2.G14 58.81,42.76 ; P2.G14 58.2,43.37 ; P2.G14 58.2,42.14 ; P2.C20 63.89,35.13 ; P2.C20 63.27,35.75 ; P2.C20 63.27,34.52 ; P2.C4 63.27,56.07 ; P2.C4 63.27,54.84 ; P2.C4 63.89,55.45 ; P2.C32 63.27,20.51 ; P2.C32 62.66,19.89 ; P2.C32 63.89,19.89 ; P2.C32 63.27,19.28 ; P2.G5 58.81,54.19 ; P2.G5 58.2,54.8 ; P2.G5 58.2,53.57 ; 56.92,56.73 56.92,57.34 ; 56.92,56.73 56.92,56.11 ; 56.92,56.73 56.31,56.73 ; 56.31,45.3 56.92,45.3 ; 56.92,45.3 56.92,45.91 ; 56.92,45.3 56.92,44.68 ; 63.27,58.65 P2.C1 ; P2.C1 63.27,59.88 ; P2.C1 62.66,59.27 ; P2.C1 63.89,59.27 ; 56.92,33.25 56.92,33.87 ; 56.92,33.87 56.92,34.48 ; 56.92,33.87 56.31,33.87 ; 61.39,32.59 P2.D22 ; P2.D22 62.01,31.98 ; P2.D22 62.01,33.21 ; P2.C25 63.89,28.79 ; P2.C25 63.27,29.4 ; P2.C25 63.27,28.17 ; P2.C25 62.66,28.79 ; P2.G32 58.2,20.51 ; P2.G32 58.2,19.28 ; P2.G32 58.81,19.89 ; 56.31,37.67 56.92,37.67 ; 56.92,37.67 56.92,38.29 ; 56.92,37.67 56.92,37.06 ; 56.92,22.43 56.92,23.05 ; 56.92,22.43 56.92,21.82 ; 56.92,22.43 56.31,22.43 ; 61.39,28.79 P2.D25 ; P2.D25 62.01,29.4 ; P2.D25 62.01,28.17 ; P2.D25 62.62,28.79 ; P2.G17 58.2,39.56 ; P2.G17 58.2,38.33 ; P2.G17 58.81,38.95 ; 63.27,43.41 P2.C13 ; P2.C13 63.27,44.64 ; P2.C13 63.89,44.02 ; P2.C16 63.27,40.83 ; P2.C16 63.27,39.6 ; P2.C16 63.89,40.22 ; 62.01,56.11 P2.D3 ; P2.D3 62.01,57.34 ; P2.D3 61.39,56.73 ; 63.27,48.49 63.27,49.1 ; 63.27,49.1 63.27,49.72 ; 63.27,49.1 63.89,49.1 ; P2.G4 58.2,56.07 ; P2.G4 58.81,55.45 ; P2.G4 58.2,54.84 ; P2.G20 58.2,35.75 ; P2.G20 58.2,34.52 ; P2.G20 58.81,35.13 ; 63.27,12.28 63.89,12.28
  BOTTOM w0.3: P2.C36 v1(62.64,14.18) 62.01,13.54 v1(62.64,12.91) 63.27,12.28
  vias: v1(36.35,53) v1(37.05,39.9) v1(37.35,53) v1(37.75,65.7) v1(37.75,61.7) v1(37.75,57.7) v1(37.75,21.7) v1(37.85,53.9) v1(38.65,38.9) v1(38.65,10.9) v1(38.75,7.2) v1(39.75,63.7) v1(39.75,59.7) v1(39.75,55.7) v1(39.75,51.7) v1(39.75,41.7) v1(39.75,37.7) v1(39.75,23.7) v1(39.75,19.7) v1(40.65,33.2) v1(40.65,32) v1(40.75,35.8) v1(40.75,34.5) v1(40.95,49) v1(40.95,48.3) v1(41.15,1.7) v1(41.35,30) v1(41.75,57.7) v1(41.75,53.7) v1(41.75,43.7) v1(41.75,39.7) v1(41.75,25.7) v1(41.75,21.7) v1(42.95,35.8) v1(42.95,34.5) v1(42.95,33.2) v1(42.95,32) v1(43.75,51.7) v1(43.75,45.7) v1(43.75,41.7) v1(43.75,37.7) v1(43.75,23.7) v1(43.75,19.7) v1(43.85,27.7) v1(44.85,36.9) v1(44.95,32) v1(45.15,1.7) v1(45.65,21.7) v1(45.75,53.7) v1(45.75,8.5) v1(45.85,48.3) v1(46.05,44.4) v1(46.05,41.7) v1(46.05,39) v1(45.95,10.8) v1(46.75,15.7) v1(46.75,14.7) v1(46.75,7.1) v1(46.85,27.9) v1(46.85,26.9) v1(47.05,37.1) v1(47.15,35.2) v1(47.25,46.2) v1(47.35,41.7) v1(47.45,44.4) v1(47.45,39) v1(47.65,15.7) v1(47.65,14.8) v1(47.75,51.7) v1(47.75,29.7) v1(48.05,9.9) v1(48.25,34.5) v1(48.45,23.6) v1(48.55,15.2) v1(48.65,36.9) v1(48.65,19.6) v1(48.75,41.7) v1(48.75,39) v1(49.15,48.1) v1(49.15,46.2) v1(49.15,44.4) v1(49.15,1.7) v1(49.25,50.3) v1(49.45,15.7) v1(49.45,14.8) v1(49.75,65.7) v1(49.75,61.7) v1(49.75,57.7) v1(49.75,53.7) v1(49.75,31.7) v1(49.95,41.7) v1(50.05,39) v1(50.05,36.9) v1(50.25,23.3) v1(50.25,19.6) v1(51.05,48.1) v1(50.95,44.4) v1(51.35,50.3) v1(51.75,63.7) v1(51.75,59.7) v1(51.75,41.7) v1(51.75,37.7) v1(51.75,33.7) v1(51.75,29.7) v1(51.75,27.7) v1(51.75,25.7) v1(51.75,8.5) v1(52.15,16.9) v1(52.45,24.2) v1(52.55,20.8) v1(52.45,10) v1(52.75,51.7) v1(52.75,7.5) v1(53.05,24.2) v1(53.15,10) v1(53.15,1.7) v1(53.25,50.3) v1(53.75,65.7) v1(53.75,61.7) v1(53.75,57.7) v1(53.75,53.7) v1(53.75,43.7) v1(53.75,39.7) v1(53.75,35.7) v1(53.75,31.7) v1(53.75,27.7) v1(53.75,25.7) v1(54.15,16.4) v1(54.25,19.1) v1(54.55,13) v1(54.65,17.9) v1(55.05,50.3) v1(55.75,63.7) v1(55.75,59.7) v1(55.75,41.7) v1(55.75,37.7) v1(55.75,33.7) v1(55.75,29.7) v1(55.85,57.9) v1(55.85,56.7) v1(55.85,19.6) v1(56.05,48.8) v1(55.95,45.2) v1(56.05,26.2) v1(56.05,22.4) v1(56.05,21.1) v1(55.95,14.8) v1(56.25,53.4) v1(57.15,1.7) v1(57.55,26.9) v1(57.55,24.3) v1(57.55,14.2) v1(57.55,12.9) v1(58.35,8.8) v1(59.05,42.7) v1(59.05,38.9) v1(59.05,35.1) v1(59.05,31.3) v1(59.05,27.5) v1(59.05,12.3) v1(59.15,54.1) v1(59.15,50.2) v1(59.15,23.7) v1(59.25,59.2) v1(59.25,55.5) v1(59.25,46.5) v1(59.75,13.7) v1(59.75,9.7) v1(59.75,5.7) v1(61.05,58) v1(61.05,52.9) v1(60.95,47.9) v1(61.05,44.2) v1(61.05,40.1) v1(61.05,36.4) v1(61.05,28.7) v1(61.15,56.7) v1(61.15,32.6) v1(61.15,1.7) v1(61.75,65.7) v1(61.75,5.7) v1(62.65,52.3) v1(62.65,29.4) v1(62.65,24.4) v1(62.65,19.3) v1(63.75,67.7) v1(63.75,63.7) v1(63.75,7.7) v1(64.05,19.3) v1(64.05,15.3) v1(64.25,54.3) v1(64.25,50.5) v1(64.25,49.2) v1(64.15,40.2) v1(64.15,39) v1(64.25,35.1) v1(64.15,33.9) v1(64.15,30) v1(64.15,28.7) v1(64.15,17.4) v1(64.15,12.3) v1(64.35,59.4) v1(64.35,55.6) v1(64.35,45.3) v1(64.35,44) v1(65.15,1.7) v1(65.75,65.7) v1(65.75,61.7) v1(65.75,57.7) v1(65.75,53.7) v1(65.75,49.7) v1(65.75,45.7) v1(65.75,41.7) v1(65.75,37.7) v1(65.75,33.7) v1(65.75,29.7) v1(65.75,25.7) v1(65.75,21.7) v1(65.75,5.7) v1(65.95,10.5) v1(66.95,11.6) v1(67.75,63.7) v1(67.75,59.7) v1(67.75,55.7) v1(67.75,51.7) v1(67.75,47.7) v1(67.75,43.7) v1(67.75,39.7) v1(67.75,35.7) v1(67.75,31.7) v1(67.75,27.7) v1(67.75,23.7) v1(67.75,19.7) v1(67.75,15.7) v1(67.75,7.7) v1(67.75,3.7)
GND_SIGNAL: length 63.2
  TOP w0.3: U2.3 9.9,9.15 ; U2.6 8.6,9.15
  TOP w0.4: 4.88,38.31 P1.5 ; P1.5 5.94,39.37 ; P1.5 5.94,37.25 ; P1.5 7,38.31 ; 26.49,42.3 TP4.1 ; TP4.1 27.55,41.24 ; TP4.1 28.61,42.3 ; TP4.1 27.55,43.36 ; 27.55,2.14 TP7.1 ; TP7.1 28.61,3.2 ; TP7.1 26.49,3.2 ; TP7.1 27.55,4.26 ; 2.34,38.31 P1.11 ; P1.11 3.4,39.37 ; P1.11 4.46,38.31 ; P1.11 3.4,37.25
  L2_GND w0.4: 27.55,41.24 TP4.1 ; TP4.1 27.55,43.36 ; TP4.1 26.49,42.3 ; TP4.1 28.61,42.3 ; TP7.1 27.55,4.26 ; TP7.1 28.61,3.2 ; TP7.1 26.49,3.2 ; TP7.1 27.55,2.14 ; P1.5 7,38.31 ; P1.5 5.94,37.25 ; P1.5 4.88,38.31 ; P1.5 5.94,39.37 ; 2.34,38.31 P1.11 ; P1.11 4.46,38.31 ; P1.11 3.4,39.37 ; P1.11 3.4,37.25
  L3_PWR w0.4: P1.11 4.46,38.31 ; P1.11 2.34,38.31 ; P1.11 3.4,37.25 ; P1.5 7,38.31 ; P1.5 5.94,37.25 ; P1.5 4.88,38.31 ; TP7.1 27.55,4.26 ; TP7.1 27.55,2.14 ; TP7.1 26.49,3.2 ; TP7.1 28.61,3.2
  BOTTOM w0.4: 3.4,37.25 P1.11 ; P1.11 3.4,39.37 ; P1.11 2.34,38.31 ; P1.11 4.46,38.31 ; P1.5 7,38.31 ; P1.5 5.94,37.25 ; P1.5 4.88,38.31 ; P1.5 5.94,39.37 ; TP7.1 28.61,3.2 ; TP7.1 27.55,2.14 ; TP7.1 27.55,4.26 ; TP7.1 26.49,3.2 ; 26.49,42.3 TP4.1 ; TP4.1 28.61,42.3 ; TP4.1 27.55,43.36 ; TP4.1 27.55,41.24
  vias: v1(1.75,63.7) v1(1.75,59.7) v1(1.75,55.7) v1(1.75,47.7) v1(1.75,43.7) v1(1.75,25.7) v1(1.75,21.7) v1(1.75,13.7) v1(1.75,9.7) v1(1.75,5.7) v1(3.75,61.7) v1(3.75,57.7) v1(3.75,53.7) v1(3.75,45.7) v1(3.75,23.7) v1(3.75,1.7) v1(5.75,63.7) v1(5.75,59.7) v1(5.75,55.7) v1(5.75,51.7) v1(5.75,47.7) v1(5.75,43.7) v1(5.75,25.7) v1(5.75,21.7) v1(7.25,36.8) v1(7.35,35.1) v1(7.35,33.9) v1(7.35,32.6) v1(7.35,31.4) v1(7.35,29.4) v1(7.45,3.3) v1(7.75,61.7) v1(7.75,57.7) v1(7.75,53.7) v1(7.75,49.7) v1(7.75,45.7) v1(7.75,41.7) v1(7.75,37.7) v1(7.75,23.7) v1(7.75,1.7) v1(8.35,3.3) v1(8.75,9.8) v1(8.75,8.9) v1(8.75,8) v1(8.75,6.9) v1(8.95,11.7) v1(9.75,63.7) v1(9.75,59.7) v1(9.75,55.7) v1(9.75,51.7) v1(9.75,47.7) v1(9.75,43.7) v1(9.75,25.7) v1(9.75,21.7) v1(9.75,9.8) v1(9.75,8.9) v1(9.75,8) v1(9.75,6.9) v1(10.35,3.3) v1(10.75,32.3) v1(11.05,30.2) v1(11.05,11.1) v1(11.05,10.4) v1(11.25,3.3) v1(11.35,35.6) v1(11.55,13.6) v1(11.75,61.7) v1(11.75,57.7) v1(11.75,53.7) v1(11.75,45.7) v1(11.75,41.7) v1(11.75,37.7) v1(11.75,27.7) v1(11.75,23.7) v1(11.75,1.7) v1(11.95,35) v1(12.25,36.6) v1(12.25,31.4) v1(13.75,63.7) v1(13.75,59.7) v1(13.75,55.7) v1(13.75,51.7) v1(13.75,47.7) v1(13.75,43.7) v1(13.75,39.7) v1(13.85,34.5) v1(13.85,33.2) v1(13.85,31.9) v1(13.75,29.7) v1(13.75,25.7) v1(13.75,21.7) v1(13.95,11) v1(13.95,10) v1(15.75,61.7) v1(15.75,57.7) v1(15.75,53.7) v1(15.75,45.7) v1(15.75,41.7) v1(15.75,37.7) v1(15.75,27.7) v1(15.75,23.7) v1(15.75,13.6) v1(15.75,3) v1(15.75,1.7) v1(16.15,9.9) v1(16.25,7.3) v1(16.45,15) v1(16.55,3) v1(16.95,8.6) v1(17.55,35.8) v1(17.55,34.5) v1(17.55,33.2) v1(17.55,32) v1(17.56,14.13) v1(17.65,7.3) v1(17.75,63.7) v1(17.75,59.7) v1(17.75,55.7) v1(17.75,51.7) v1(17.75,47.7) v1(17.75,43.7) v1(17.75,39.7) v1(17.75,29.7) v1(17.75,25.7) v1(17.75,21.7) v1(17.75,9.9) v1(19.75,61.7) v1(19.75,57.7) v1(19.75,53.7) v1(19.75,50.3) v1(19.75,45.7) v1(19.75,41.7) v1(19.75,37.7) v1(19.75,27.7) v1(19.75,23.7) v1(19.75,1.7) v1(20.75,13.4) v1(21.75,63.7) v1(21.75,59.7) v1(21.75,55.7) v1(21.75,51.7) v1(21.75,47.7) v1(21.75,43.7) v1(21.75,39.7) v1(21.75,29.7) v1(21.75,25.7) v1(21.75,21.7) v1(21.85,35.8) v1(21.85,34.5) v1(21.85,33.2) v1(21.85,32) v1(21.95,13.4) v1(23.75,61.7) v1(23.75,57.7) v1(23.75,53.7) v1(23.75,45.7) v1(23.75,41.7) v1(23.75,37.7) v1(23.75,27.7) v1(23.75,23.7) v1(23.75,1.7) v1(23.85,50.3) v1(25.75,63.7) v1(25.75,59.7) v1(25.75,55.7) v1(25.75,51.7) v1(25.75,39.7) v1(25.75,25.7) v1(25.75,21.7) v1(27.55,15.8) v1(27.55,14.8) v1(27.75,61.7) v1(27.75,57.7) v1(27.75,53.7) v1(27.75,37.7) v1(27.75,30) v1(27.75,23.7) v1(27.75,1.7) v1(28.15,50.3) v1(28.05,48.8) v1(28.15,8.9) v1(28.45,35.8) v1(28.45,34.5) v1(28.55,33.2) v1(28.55,32) v1(29.75,63.7) v1(29.75,59.7) v1(29.75,55.7) v1(29.75,51.7) v1(29.75,21.7) v1(30.15,10.6) v1(30.05,7) v1(30.65,52.2) v1(30.55,38.9) v1(31.35,39.7) v1(31.55,53) v1(31.75,61.7) v1(31.75,57.7) v1(32.35,39.7) v1(32.55,53)
3P3V_FMC: length 5.1
  TOP w0.5: R2.1 v1(42.75,5.6)
  L3_PWR w0.4: TP8.1 40.91,3.2 ; TP8.1 39.85,2.14 ; TP8.1 39.85,4.26 ; TP8.1 38.79,3.2
  vias: v1(49.55,9) v1(50.15,9) v1(54.35,6.4) v1(54.35,5.8) v1(61.05,12.3) v1(61.95,8.9) v1(63.85,10.4)
3P3V_ISO: length 1
  TOP w0.3: R28.1 14.16,7.35 C15.1
3P3VAUX: length 7.1
  TOP w0.4: v1(59.75,19) 59.1,19.65 R35.1 57.75,18.4 TP9.1
  BOTTOM w0.4: P2.D32 60.65,19.89 v1(59.75,19)
CLK0_M2C_P: length 12.7
  TOP w0.2: v1(56.15,55.45) 48.52,55.45 arc(46.44,55.87) R34.2
  BOTTOM w0.2: 56.92,55.45 v1(56.15,55.45)
CNV: length 2.4
  TOP w0.2: R23.2 P1.1
CNV_FMC: length 27.5
  TOP w0.2: v1(55.95,46.56) 54.12,46.56 50.65,43.1 50.65,36 45.98,31.32 R13.1
  BOTTOM w0.2: 56.92,46.56 v1(55.95,46.56)
CNV_ISO: length 24
  TOP w0.2: U1.15 13.07,31.32 9.9,28.15 R23.1
FMC_VIO: length 2.5
  TOP w0.5: R1.2 v1(41.2,9) ; R4.2 v1(44.3,9) ; R2.2 v1(42.75,9)
  vias: v1(40.35,47) v1(40.35,46.4) v1(40.65,28.7) v1(40.65,28.1)
GA0: length 4.8
  TOP w0.4: U8.2 v1(60.72,18)
  BOTTOM w0.2: v1(60.72,18) 62.63,18 P2.C34
GA1: length 5.3
  TOP w0.4: U8.1 v1(59.45,18)
  BOTTOM w0.2: P2.D35 61.36,16.09 v1(59.45,18)
LT3999_SYNC: length 3
  TOP w0.2: U6.8 48.55,17.69 47.05,19.19 JP2.2
MUX_A0: length 5.4
  TOP w0.2: P1.9 4.63,32 R32.1
MUX_A0_FMC: length 21.6
  TOP w0.2: U7.2 v1(38.18,49.68)
  BOTTOM w0.2: 58.2,49.1 57.62,49.68 v1(38.18,49.68)
MUX_A0_ISO: length 36.2
  TOP w0.2: R32.2 v1(9.93,32) ; U7.7 v1(30.82,49.68)
  BOTTOM w0.2: v1(9.93,32) 9.93,33.58 10.65,34.3 10.65,42.8 17.53,49.68 v1(30.82,49.68)
MUX_A1: length 5.5
  TOP w0.2: R33.1 4.67,34.5 P1.10
MUX_A1_FMC: length 21.6
  TOP w0.2: U7.3 v1(38.18,50.95)
  BOTTOM w0.2: v1(38.18,50.95) 57.5,50.95 P2.G7
MUX_A1_ISO: length 34.7
  TOP w0.2: R33.2 v1(9.93,34.5) ; U7.6 v1(30.82,50.95)
  BOTTOM w0.2: v1(30.82,50.95) 17.87,50.95 9.93,43 v1(9.93,34.5)
PMOD_VCC: length 10.6
  L3_PWR w0.4: P1.6 5.94,41.91 ; P1.6 7,40.85 ; P1.6 4.88,40.85 ; P1.12 3.4,41.91 ; P1.12 2.34,40.85 ; P1.12 4.46,40.85 ; 15.85,10.9 TP6.1 ; TP6.1 17.97,10.9 ; TP6.1 16.91,11.96 ; TP6.1 16.91,9.84
  vias: v1(19.25,8) v1(19.25,7.4) v1(28.35,28.7) v1(28.35,28.1) v1(28.65,47) v1(28.65,46.4)
SCLK: length 3.3
  TOP w0.2: P1.4 R26.2 R27.2
SCLK_FMC: length 34.7
  TOP w0.2: v1(60.05,52.9) 60.05,51.7 59.45,51.1 54.95,51.1 48.05,44.2 48.05,37.2 44.72,33.87 R15.1
  BOTTOM w0.2: P2.G6 60.03,52.91 v1(60.05,52.9)
SCLK_ISO: length 23.5
  TOP w0.2: R26.1 10.28,35.77 12.19,33.87 U1.13
SCLK_RET_FMC: length 33.6
  TOP w0.2: R16.1 43.98,35.13 46.75,37.9 46.75,44.7 53.85,51.8 v1(59.05,51.8)
  BOTTOM w0.2: P2.D8 60.58,51.8 v1(59.05,51.8)
SCLK_RETURN: length 23.3
  TOP w0.2: U1.12 12.71,35.13 11.15,36.7 9.23,36.7 R27.1
SDI: length 2.4
  TOP w0.2: P1.2 R24.2
SDI_FMC: length 28.6
  TOP w0.2: R14.1 45.45,32.59 49.35,36.5 49.35,43.67 v1(56.05,50.38)
  BOTTOM w0.2: 56.92,50.38 v1(56.05,50.38)
SDI_ISO: length 23.5
  TOP w0.2: U1.14 12.35,32.59 10.44,30.69 R24.1
SDO: length 2.4
  TOP w0.2: R25.2 8.3,33.23 P1.3
SDO_FMC: length 27.9
  TOP w0.2: v1(56.26,52.31) 52.46,52.31 45.45,45.3 45.45,38.5 43.35,36.41 R17.1
  BOTTOM w0.2: 56.92,51.65 v1(56.26,52.31)
SDO_ISO: length 24
  TOP w0.2: U1.11 v1(14.35,36.41) ; R25.1 v1(11.05,33.2)
  BOTTOM w0.2: v1(11.05,33.2) 14.25,36.41 v1(14.35,36.41)
UNNAMED_7_ADLT3999_I29_RBIAS: length 1.3
  TOP w0.2: U6.2 R8.1
UNNAMED_7_ADLT3999_I29_RT: length 1.5
  TOP w0.2: U6.7 49.05,17.75 R7.1
UNNAMED_7_ADP7105_I140_PG: length 2.2
  TOP w0.2: U2.7 6.8,8.65 6.4,9.05 R22.2
UNNAMED_7_ADP7105_I140_SENSE: length 5.4
  TOP w0.3: 12.1,8.65 U2.2 ; 12.1,8.65 12.5,8.25 R28.2 ; 12.1,8.65 12.6,9.15 R29.1 13.9,9.15 14.2,8.85 R30.1
UNNAMED_7_ADP7105_I140_SS: length 2.7
  TOP w0.3: C14.1 12.24,9.99 11.9,9.65 U2.4
UNNAMED_7_ADUM120N_I19_VDD1: length 4.2
  TOP w0.4: 37.66,44.08 TP2.1 ; TP2.1 36.6,45.14 ; TP2.1 37.66,46.2 ; TP2.1 38.72,45.14
UNNAMED_7_ADUM120N_I19_VDD2: length 4.2
  TOP w0.4: 31.35,44.08 TP3.1 ; TP3.1 32.41,45.14 ; TP3.1 30.29,45.14 ; TP3.1 31.35,46.2
UNNAMED_7_ADUM152N_I128_VIA: length 1.9
  TOP w0.2: R13.2 U1.2
UNNAMED_7_ADUM152N_I128_VIB: length 1.9
  TOP w0.2: R14.2 U1.3
UNNAMED_7_ADUM152N_I128_VIC: length 1.9
  TOP w0.2: R15.2 U1.4
UNNAMED_7_ADUM152N_I128_VOD: length 1.9
  TOP w0.2: R16.2 U1.5
UNNAMED_7_ADUM152N_I128_VOE: length 1.9
  TOP w0.2: R17.2 U1.6
UNNAMED_7_CAP_I3_N1: length 5
  TOP w0.2: U4.3 50.45,8 v1(50.95,8.5)
  BOTTOM w0.2: v1(50.95,8.5) 50.95,7.1 v1(52.65,5.4)
UNNAMED_7_CAP_I51_N1: length 4.2
  TOP w0.4: VDD2.1 32.43,27.1 ; VDD2.1 30.31,27.1 ; VDD2.1 31.37,28.16 ; VDD2.1 31.37,26.04
UNNAMED_7_CAP_I54_N1: length 4.2
  TOP w0.4: VDD1.1 37.62,28.16 ; VDD1.1 38.68,27.1 ; VDD1.1 36.55,27.1 ; VDD1.1 37.62,26.04
UNNAMED_7_CAP_I146_N2: length 1.2
  TOP w0.3: R30.2 15.1,7.41 C15.2
UNNAMED_7_CNTP1P_I189_N1: length 2.2
  TOP w0.4: SYNC.1 JP2.3
UNNAMED_8_CAP_I16_N2: length 2.7
  TOP w0.2: U8.8 57.76,21.14 R35.2 C17.2
UNNAMED_8_CN160PCDGHV2_I11_TDI: length 1.3
  BOTTOM w0.2: P2.D30 P2.D31
UNNAMED_8_CN160PCDGHV2_I22_SCL: length 4.1
  TOP w0.2: v1(64.19,22.43) 64.16,22.46 62.52,22.46 61.98,21.93 U8.6
  BOTTOM w0.2: P2.C30 v1(64.19,22.43)
UNNAMED_8_CN160PCDGHV2_I22_SDA: length 1.9
  TOP w0.2: U8.5 63.28,21.16 v1(64.19,21.16)
  BOTTOM w0.2: P2.C31 v1(64.19,21.16)
UNNAMED_8_CNBNC5P_I2_CNTR: length 4.5
  TOP w0.2: J1.1 R34.1
UNNAMED_8_DIOLED_I20_P: length 1.6
  TOP w0.2: R36.2 DS1.A
VAJD_FMC: length 23.7
  TOP w0.5: R1.1 v1(41.2,5.6)
  BOTTOM w0.5: P2.G39 56.92,9.73 56.69,9.73 53.65,6.7 53.65,3.87 VADJ.1 47.58,3.27 46.35,4.5 42.3,4.5 v1(41.2,5.6)
XP2: length 3.8
  BOTTOM w0.5: v1(50.05,12.9) 50.05,14.15 51.14,15.24 VIN.1
  vias: v1(43.55,16) v1(43.55,15.3) v1(43.55,14.6) v1(49.05,12.9)

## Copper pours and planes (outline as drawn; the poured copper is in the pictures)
1V8VIO_FMC on TOP: 48.55,6.3 48.55,5.1 43.75,5.1 43.75,6.9 44.95,6.9 44.95,6.3
4V_ISO on TOP: 15.05,19.3 15.05,17.1 10.45,17.1 9.85,16.5 9.85,14.6 8.43,14.6 8.43,16.12 6.95,17.6 6.95,19 7.25,19.3
+12V_FMC on TOP: 51.05,13.2 51.05,11.1 52.45,11.1 52.45,13.2
+12V_FMC on BOTTOM: 62.95,16.8 62.95,12.8 64.65,12.8 64.65,16.8
+12V_FMC on L3_PWR: 53.55,18.2 68.24,18.2 68.24,0.76 60.55,0.76 60.55,5.6 64.55,5.6 64.55,13.3 59.55,13.3 59.55,10.8 48.15,10.8 48.15,13.2 53.55,13.2
GND_POWER on TOP: 35.95,68.24 68.24,68.24 68.24,0.76 35.95,0.76 35.95,36.3 37.05,36.3 37.05,31.1 37.95,31.1 37.95,30.4 39.45,30.4 39.45,29.1 39.95,29.1 39.95,30.4 40.35,30.4 40.35,37 38.35,37 38.35,38.6 35.95,38.6 35.95,50.6 37.75,50.6 37.75,51.9 35.95,51.9 ; 8 cut-outs
GND_POWER on BOTTOM: 35.95,68.24 68.24,68.24 68.24,0.76 35.95,0.76 ; 61 cut-outs
GND_POWER on L2_GND, L3_PWR: 35.95,68.24 68.24,68.24 68.24,0.76 35.95,0.76
GND_SIGNAL on TOP: 0.76,68.24 32.85,68.24 32.85,51.9 31.25,51.9 31.25,51.4 32.85,51.4 32.85,38.6 30.65,38.6 30.65,30.4 32.85,30.4 32.85,0.76 0.76,0.76 ; 8 cut-outs
GND_SIGNAL on BOTTOM, L2_GND: 0.76,68.24 32.85,68.24 32.85,0.76 0.76,0.76
GND_SIGNAL on L3_PWR: 0.76,68.24 32.85,68.24 32.85,0.76 0.76,0.76 ; 1 cut-out
3P3V_FMC on TOP: 49.05,10.62 49.05,8.6 50.34,8.6 50.55,8.81 50.55,10.62
3P3V_FMC on TOP: 53.45,5.5 54.75,5.5 54.75,6.7 53.45,6.7
3P3V_FMC on BOTTOM: 60.65,15.1 62.35,15.1 62.35,11.7 64.65,11.7 64.65,8.6 60.65,8.6
3P3V_FMC on L3_PWR: 60.05,12.6 64.15,12.6 64.15,6.2 59.85,6.2 59.85,0.8 37.95,0.8 37.95,7.8 42.35,7.8 42.35,6 48.15,6 48.15,10.3 60.05,10.3
3P3V_ISO on TOP: 10.35,8.2 10.35,7.9 10.85,7.4 11.45,7.4 12.65,6.2 12.65,3.8 17.29,3.8 17.29,6.6 14.05,6.6 13.55,7.1 13.55,7.6 12.55,7.6 11.95,8.2
FMC_VIO on TOP: 40.95,28 40.95,28.8 40.75,29 39.75,29 39.75,27.8 40.75,27.8
FMC_VIO on TOP: 40.65,46.3 40.65,47.1 40.45,47.3 39.45,47.3 39.45,46.1 40.45,46.1
FMC_VIO on L3_PWR: 36.15,47.4 46.15,47.4 46.15,31.2 42.95,31.2 42.95,24.6 47.35,24.6 47.35,6.6 43.05,6.6 43.05,8.6 36.15,8.6
PMOD_VCC on TOP: 28.35,47.1 28.35,46.3 28.55,46.1 29.55,46.1 29.55,47.3 28.55,47.3
PMOD_VCC on TOP: 21.1,7.1 21.1,8.5 18.95,8.5 18.95,7.1
PMOD_VCC on TOP: 28.05,28.8 28.05,28 28.25,27.8 29.25,27.8 29.25,29 28.25,29
PMOD_VCC on L3_PWR: 0.85,47.8 29.05,47.8 29.05,25.8 20.35,25.8 20.35,6.7 14.85,6.7 14.85,39.6 0.85,39.6
UNNAMED_7_ADP7105_I140_VIN on TOP: 7.88,9.6 5.35,9.6 5.15,9.4 5.15,8.4 5.35,8.2 8.05,8.2 8.05,8 7.45,7.4 6.25,7.4 5.95,7.1 5.95,3.7 3.75,3.7 3.75,13.9 5.95,16.1 7.88,16.1
UNNAMED_7_ADUM120N_I19_VDD1 on TOP: 35.95,48.8 35.95,43.8 39.05,43.8 39.05,48.8
UNNAMED_7_ADUM120N_I19_VDD2 on TOP: 29.95,48.8 29.95,43.8 32.85,43.8 32.85,48.8
UNNAMED_7_CAP_I3_N1 on TOP: 49.15,6.3 49.15,5.1 53.05,5.1 53.05,6.3
UNNAMED_7_CAP_I38_N1 on TOP: 25.65,19.3 15.85,19.3 15.85,17.1 23.05,17.1 23.25,16.9 23.25,11.9 25.65,11.9
UNNAMED_7_CAP_I51_N1 on TOP: 29.65,30.4 29.65,25.8 32.75,25.8 32.75,30.4
UNNAMED_7_CAP_I54_N1 on TOP: 36.15,30.4 36.15,25.8 39.35,25.8 39.35,30.4
UNNAMED_7_CAP_I136_N2 on TOP: 15.05,14.3 15.05,16.1 10.55,16.1 10.55,14.3
UNNAMED_7_CNTP1P_I212_N1 on TOP: 18.21,6.54 18.21,2.4 22.05,2.4 22.05,6.54
UNNAMED_7_RESJMPRSHRT3P_I198_A on TOP: 10.65,13.5 10.65,14.1 8.43,14.1 8.43,12.77 9.48,12.77 10.55,11.7 18.45,11.7 21.65,8.5 21.65,7.1 22.95,7.1 22.95,9.2 19.25,12.9 11.25,12.9
XP1 on TOP: 37.95,13.7 46.95,13.7 47.35,14.1 47.65,14.1 47.65,13.1 46.55,12 37.95,12
XP2 on TOP: 48.45,14.1 48.45,13.05 49.05,12.45 49.05,11.1 50.55,11.1 50.55,13.2 49.9,13.2 49.7,13 49.35,13 49.15,13.2 49.15,14.1
XP2 on TOP: 44.15,16.3 44.15,14.2 37.95,14.2 37.95,16.3
XP2 on BOTTOM: 43.25,16.3 44.25,16.3 44.45,16.1 44.45,13.8 44.85,13.4 50.4,13.4 50.4,11.8 43.85,11.8 43.25,12.4
XP3 on TOP: 37.95,16.8 46.95,16.8 47.35,16.4 47.65,16.4 47.65,17.4 46.55,18.5 37.95,18.5
XP4 on TOP: 30.95,17.1 30.95,18.5 26.55,18.5 26.55,17.1
XP6 on TOP: 30.95,12 30.95,13.4 26.55,13.4 26.55,12

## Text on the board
Ref Des/Silkscreen Bottom: 08-071850 REV B Z | SECONDARY SIDE
User.Comments: SMOOTHEN EDGES AND FREE FROM BURRS AFTER DEPANELIZATION PROCESS. | 7.    SOLDER FILLET BOARD ETCH TO CONNECTOR TOP AND BOTTOM | 8.    INSTALL STANDOFFS (M031821) AND HEX NUTS (M017432). | 9.    ADD SOLDER BLOB ON POSITIONS 1 AND 2 OF JP1, JP4 & JP5. | 6.    BOARDS TO BE SHIPPED SINGULATED AFTER ASSEMBLY PROCESS. | SEE NOTE 8 | (2 PLACES)
Ref Des/Assembly Top: 1 | 2 | 3 | C | A
Ref Des/Silkscreen Top: PMOD_VCC | 3P3V ISO | GND_SIGNAL | 3P3V | GND_POWER | HALF_CNV | 3P3VAUX | 3 | 1 | C | A | +12V | +12V_FMC | 2 | PRIMARY SIDE | 08-071850 REV B Z | PMB0002: ISOLATED FMC-to-PMOD BOARD
PAGE_OUTLINE: 15JUN22 | B | AS PER ECR-110925 | 28OCT22 | N.GARLITOS | CUSTOMER EVALUATION Z | FMC-PMOD_ISO BOARD
DIMENSION: " " | (REF) | +0.0508/-0 | DIA MAX
User.10: L2 GND | 08-      -07
User.11: 08-      -08 | L3 Internal PWR
User.13: 15.    BOARDS TO BE SHIPPED IN ARRAY AND KEEP INTACT. | 16.    PANEL TO BE SUBJECTED TO CUSTOMER'S APPROVAL. | 17.    PANELED SOLDER PASTE STENCIL SHOULD BE SENT TO THE CUSTOMER.
User.14: see | note | 1
User.15: L3 PWR | 08-      -08
User.16: LAYER3 | 08-      -09
User.34: FIGURE | SIZE | 0.254 | 1.016 | 1.524 | 1.651 | 1.27 | 3.175 | DRILL CHART: TOP to BOTTOM | FINISHED HOLES IN MILLIMETERS | PLATED | NON-PLATED | QTY | 491 | 27 | 1 | 4 | 2 | TOLERANCE/NOTES
